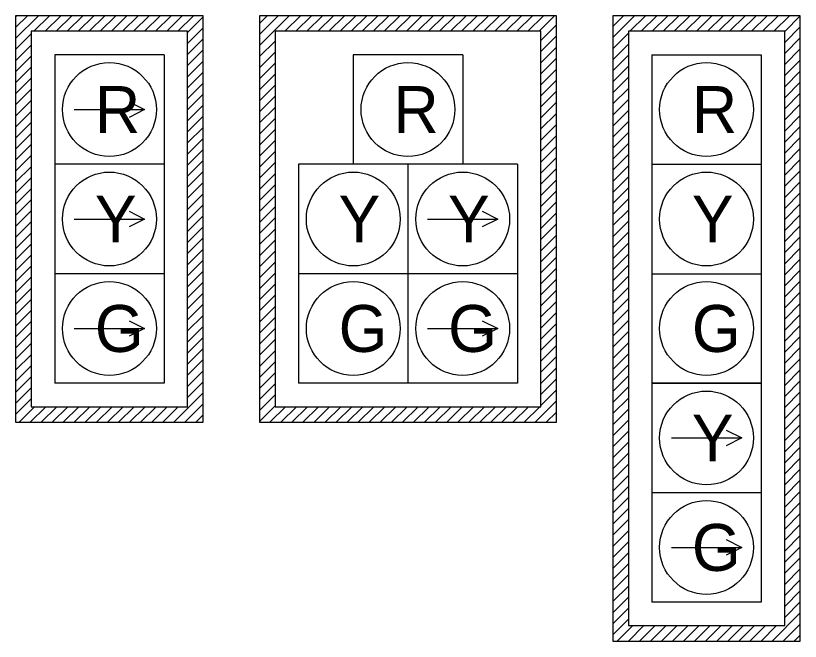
# Model space of a CAD drawing. Extents: x 1736833 to 1738623, y 544707 to 545544.
# Drawn here: x 1737177.5 to 1737277.8, y 545241.6 to 545321.6 of the extents above; entities that cross this region are included whole.
import ezdxf

# ---------------------------------------------------------------- set-up
doc = ezdxf.new("R2010")
doc.units = 0
doc.layers.add('T_Drafting', color=7, linetype='Continuous')

msp = doc.modelspace()

# ---------------------------------------------------------------- linework, layer by layer
at = {"layer": 'T_Drafting'}
for p, q in [((1737201.45, 545321.61), (1737177.45, 545321.61)), ((1737177.45, 545321.61), (1737177.45, 545269.61)), ((1737177.45, 545318.68), (1737180.38, 545321.61)), ((1737177.45, 545320.1), (1737178.97, 545321.61)), ((1737177.45, 545321.51), (1737177.55, 545321.61)), ((1737179.79, 545319.61), (1737181.79, 545321.61)), ((1737181.21, 545319.61), (1737183.21, 545321.61)), ((1737182.62, 545319.61), (1737184.62, 545321.61)), ((1737184.04, 545319.61), (1737186.04, 545321.61)), ((1737185.45, 545319.61), (1737187.45, 545321.61)), ((1737186.87, 545319.61), (1737188.87, 545321.61)), ((1737188.28, 545319.61), (1737190.28, 545321.61)), ((1737189.69, 545319.61), (1737191.69, 545321.61)), ((1737191.11, 545319.61), (1737193.11, 545321.61)), ((1737192.52, 545319.61), (1737194.52, 545321.61)), ((1737193.94, 545319.61), (1737195.94, 545321.61)), ((1737195.35, 545319.61), (1737197.35, 545321.61)), ((1737196.77, 545319.61), (1737198.77, 545321.61)), ((1737198.18, 545319.61), (1737200.18, 545321.61)), ((1737201.45, 545269.61), (1737201.45, 545321.61)), ((1737246.64, 545321.61), (1737208.64, 545321.61)), ((1737208.64, 545321.61), (1737208.64, 545269.61)), ((1737208.64, 545317.79), (1737212.46, 545321.61)), ((1737208.64, 545319.2), (1737211.05, 545321.61)), ((1737208.64, 545320.62), (1737209.63, 545321.61)), ((1737211.88, 545319.61), (1737213.88, 545321.61)), ((1737213.29, 545319.61), (1737215.29, 545321.61)), ((1737214.71, 545319.61), (1737216.71, 545321.61)), ((1737216.12, 545319.61), (1737218.12, 545321.61)), ((1737217.53, 545319.61), (1737219.53, 545321.61)), ((1737218.95, 545319.61), (1737220.95, 545321.61)), ((1737220.36, 545319.61), (1737222.36, 545321.61)), ((1737221.78, 545319.61), (1737223.78, 545321.61)), ((1737223.19, 545319.61), (1737225.19, 545321.61)), ((1737224.6, 545319.61), (1737226.6, 545321.61)), ((1737226.02, 545319.61), (1737228.02, 545321.61)), ((1737227.43, 545319.61), (1737229.43, 545321.61)), ((1737228.85, 545319.61), (1737230.85, 545321.61)), ((1737230.26, 545319.61), (1737232.26, 545321.61)), ((1737231.68, 545319.61), (1737233.68, 545321.61)), ((1737233.09, 545319.61), (1737235.09, 545321.61)), ((1737234.5, 545319.61), (1737236.5, 545321.61)), ((1737235.92, 545319.61), (1737237.92, 545321.61)), ((1737237.33, 545319.61), (1737239.33, 545321.61)), ((1737238.75, 545319.61), (1737240.75, 545321.61)), ((1737240.16, 545319.61), (1737242.16, 545321.61)), ((1737241.58, 545319.61), (1737243.58, 545321.61)), ((1737242.99, 545319.61), (1737244.99, 545321.61)), ((1737244.4, 545319.61), (1737246.4, 545321.61)), ((1737246.64, 545269.61), (1737246.64, 545321.61)), ((1737277.83, 545321.61), (1737253.83, 545321.61)), ((1737253.83, 545321.61), (1737253.83, 545241.61)), ((1737253.83, 545318.81), (1737256.63, 545321.61)), ((1737253.83, 545320.22), (1737255.22, 545321.61)), ((1737256.04, 545319.61), (1737258.04, 545321.61)), ((1737257.46, 545319.61), (1737259.46, 545321.61)), ((1737258.87, 545319.61), (1737260.87, 545321.61)), ((1737260.29, 545319.61), (1737262.29, 545321.61)), ((1737261.7, 545319.61), (1737263.7, 545321.61)), ((1737263.11, 545319.61), (1737265.11, 545321.61)), ((1737264.53, 545319.61), (1737266.53, 545321.61)), ((1737265.94, 545319.61), (1737267.94, 545321.61)), ((1737267.36, 545319.61), (1737269.36, 545321.61)), ((1737268.77, 545319.61), (1737270.77, 545321.61)), ((1737270.19, 545319.61), (1737272.19, 545321.61)), ((1737271.6, 545319.61), (1737273.6, 545321.61)), ((1737273.01, 545319.61), (1737275.01, 545321.61)), ((1737274.43, 545319.61), (1737276.43, 545321.61)), ((1737275.83, 545319.59), (1737277.83, 545321.59)), ((1737277.83, 545241.61), (1737277.83, 545321.61)), ((1737199.45, 545319.47), (1737201.45, 545321.47)), ((1737199.45, 545318.06), (1737201.45, 545320.06)), ((1737244.64, 545318.43), (1737246.64, 545320.43)), ((1737275.83, 545318.18), (1737277.83, 545320.18)), ((1737177.45, 545317.27), (1737179.45, 545319.27)), ((1737199.45, 545316.64), (1737201.45, 545318.64)), ((1737244.64, 545317.02), (1737246.64, 545319.02)), ((1737253.83, 545317.39), (1737255.83, 545319.39)), ((1737275.83, 545316.76), (1737277.83, 545318.76)), ((1737177.45, 545315.85), (1737179.45, 545317.85)), ((1737208.64, 545316.37), (1737210.64, 545318.37)), ((1737244.64, 545315.6), (1737246.64, 545317.6)), ((1737253.83, 545315.98), (1737255.83, 545317.98)), ((1737196.45, 545316.61), (1737182.45, 545316.61)), ((1737182.45, 545316.61), (1737182.45, 545302.61)), ((1737196.45, 545316.61), (1737196.45, 545302.61)), ((1737199.45, 545315.23), (1737201.45, 545317.23)), ((1737208.64, 545314.96), (1737210.64, 545316.96)), ((1737234.64, 545316.61), (1737220.64, 545316.61)), ((1737220.64, 545316.61), (1737220.64, 545302.61)), ((1737234.64, 545316.61), (1737234.64, 545302.61)), ((1737253.83, 545314.56), (1737255.83, 545316.56)), ((1737258.83, 545316.61), (1737272.83, 545316.61)), ((1737258.83, 545316.61), (1737258.83, 545302.61)), ((1737272.83, 545316.61), (1737272.83, 545302.61)), ((1737275.83, 545315.35), (1737277.83, 545317.35)), ((1737177.45, 545314.44), (1737179.45, 545316.44)), ((1737199.45, 545313.81), (1737201.45, 545315.81)), ((1737208.64, 545313.54), (1737210.64, 545315.54)), ((1737244.64, 545314.19), (1737246.64, 545316.19)), ((1737275.83, 545313.94), (1737277.83, 545315.94)), ((1737177.45, 545313.03), (1737179.45, 545315.03)), ((1737244.64, 545312.77), (1737246.64, 545314.77)), ((1737253.83, 545313.15), (1737255.83, 545315.15)), ((1737177.45, 545311.61), (1737179.45, 545313.61)), ((1737199.45, 545312.4), (1737201.45, 545314.4)), ((1737208.64, 545312.13), (1737210.64, 545314.13)), ((1737253.83, 545311.74), (1737255.83, 545313.74)), ((1737275.83, 545312.52), (1737277.83, 545314.52)), ((1737199.45, 545310.98), (1737201.45, 545312.98)), ((1737208.64, 545310.72), (1737210.64, 545312.72)), ((1737244.64, 545311.36), (1737246.64, 545313.36)), ((1737275.83, 545311.11), (1737277.83, 545313.11)), ((1737177.45, 545310.2), (1737179.45, 545312.2)), ((1737199.45, 545309.57), (1737201.45, 545311.57)), ((1737244.64, 545309.95), (1737246.64, 545311.95)), ((1737253.83, 545310.32), (1737255.83, 545312.32)), ((1737275.83, 545309.69), (1737277.83, 545311.69)), ((1737177.45, 545308.78), (1737179.45, 545310.78)), ((1737208.64, 545309.3), (1737210.64, 545311.3)), ((1737244.64, 545308.53), (1737246.64, 545310.53)), ((1737253.83, 545308.91), (1737255.83, 545310.91)), ((1737184.95, 545309.61), (1737193.95, 545309.61)), ((1737199.45, 545308.16), (1737201.45, 545310.16)), ((1737208.64, 545307.89), (1737210.64, 545309.89)), ((1737275.83, 545308.28), (1737277.83, 545310.28)), ((1737177.45, 545307.37), (1737179.45, 545309.37)), ((1737199.45, 545306.74), (1737201.45, 545308.74)), ((1737244.64, 545307.12), (1737246.64, 545309.12)), ((1737253.83, 545307.49), (1737255.83, 545309.49)), ((1737275.83, 545306.86), (1737277.83, 545308.86)), ((1737177.45, 545305.96), (1737179.45, 545307.96)), ((1737208.64, 545306.47), (1737210.64, 545308.47)), ((1737244.64, 545305.7), (1737246.64, 545307.7)), ((1737253.83, 545306.08), (1737255.83, 545308.08)), ((1737177.45, 545304.54), (1737179.45, 545306.54)), ((1737199.45, 545305.33), (1737201.45, 545307.33)), ((1737208.64, 545305.06), (1737210.64, 545307.06)), ((1737253.83, 545304.66), (1737255.83, 545306.66)), ((1737275.83, 545305.45), (1737277.83, 545307.45)), ((1737199.45, 545303.91), (1737201.45, 545305.91)), ((1737208.64, 545303.64), (1737210.64, 545305.64)), ((1737244.64, 545304.29), (1737246.64, 545306.29)), ((1737275.83, 545304.04), (1737277.83, 545306.04)), ((1737177.45, 545303.13), (1737179.45, 545305.13)), ((1737199.45, 545302.5), (1737201.45, 545304.5)), ((1737244.64, 545302.88), (1737246.64, 545304.88)), ((1737253.83, 545303.25), (1737255.83, 545305.25)), ((1737275.83, 545302.62), (1737277.83, 545304.62)), ((1737177.45, 545301.71), (1737179.45, 545303.71)), ((1737208.64, 545302.23), (1737210.64, 545304.23)), ((1737253.83, 545301.84), (1737255.83, 545303.84)), ((1737196.45, 545302.61), (1737182.45, 545302.61)), ((1737182.45, 545302.61), (1737182.45, 545288.61)), ((1737196.45, 545302.61), (1737196.45, 545288.61)), ((1737199.45, 545301.08), (1737201.45, 545303.08)), ((1737208.64, 545300.82), (1737210.64, 545302.82)), ((1737227.64, 545302.61), (1737213.64, 545302.61)), ((1737213.64, 545302.61), (1737213.64, 545288.61)), ((1737227.64, 545302.61), (1737227.64, 545288.61)), ((1737241.64, 545302.61), (1737227.64, 545302.61)), ((1737227.64, 545302.61), (1737227.64, 545288.61)), ((1737241.64, 545302.61), (1737241.64, 545288.61)), ((1737244.64, 545301.46), (1737246.64, 545303.46)), ((1737258.83, 545302.61), (1737272.83, 545302.61)), ((1737258.83, 545302.61), (1737258.83, 545288.61)), ((1737272.83, 545302.61), (1737272.83, 545288.61)), ((1737275.83, 545301.21), (1737277.83, 545303.21)), ((1737177.45, 545300.3), (1737179.45, 545302.3)), ((1737199.45, 545299.67), (1737201.45, 545301.67)), ((1737244.64, 545300.05), (1737246.64, 545302.05)), ((1737253.83, 545300.42), (1737255.83, 545302.42)), ((1737275.83, 545299.79), (1737277.83, 545301.79)), ((1737177.45, 545298.88), (1737179.45, 545300.88)), ((1737208.64, 545299.4), (1737210.64, 545301.4)), ((1737244.64, 545298.63), (1737246.64, 545300.63)), ((1737253.83, 545299.01), (1737255.83, 545301.01)), ((1737199.45, 545298.26), (1737201.45, 545300.26)), ((1737208.64, 545297.99), (1737210.64, 545299.99)), ((1737253.83, 545297.59), (1737255.83, 545299.59)), ((1737275.83, 545298.38), (1737277.83, 545300.38)), ((1737177.45, 545297.47), (1737179.45, 545299.47)), ((1737199.45, 545296.84), (1737201.45, 545298.84)), ((1737208.64, 545296.57), (1737210.64, 545298.57)), ((1737244.64, 545297.22), (1737246.64, 545299.22)), ((1737275.83, 545296.97), (1737277.83, 545298.97)), ((1737177.45, 545296.06), (1737179.45, 545298.06)), ((1737244.64, 545295.8), (1737246.64, 545297.8)), ((1737253.83, 545296.18), (1737255.83, 545298.18)), ((1737275.83, 545295.55), (1737277.83, 545297.55)), ((1737177.45, 545294.64), (1737179.45, 545296.64)), ((1737199.45, 545295.43), (1737201.45, 545297.43)), ((1737208.64, 545295.16), (1737210.64, 545297.16)), ((1737253.83, 545294.76), (1737255.83, 545296.76)), ((1737184.95, 545295.61), (1737193.95, 545295.61)), ((1737199.45, 545294.01), (1737201.45, 545296.01)), ((1737208.64, 545293.75), (1737210.64, 545295.75)), ((1737230.14, 545295.61), (1737239.14, 545295.61)), ((1737244.64, 545294.39), (1737246.64, 545296.39)), ((1737275.83, 545294.14), (1737277.83, 545296.14)), ((1737177.45, 545293.23), (1737179.45, 545295.23)), ((1737199.45, 545292.6), (1737201.45, 545294.6)), ((1737244.64, 545292.98), (1737246.64, 545294.98)), ((1737253.83, 545293.35), (1737255.83, 545295.35)), ((1737275.83, 545292.72), (1737277.83, 545294.72)), ((1737177.45, 545291.81), (1737179.45, 545293.81)), ((1737208.64, 545292.33), (1737210.64, 545294.33)), ((1737244.64, 545291.56), (1737246.64, 545293.56)), ((1737253.83, 545291.94), (1737255.83, 545293.94)), ((1737199.45, 545291.19), (1737201.45, 545293.19)), ((1737208.64, 545290.92), (1737210.64, 545292.92)), ((1737253.83, 545290.52), (1737255.83, 545292.52)), ((1737275.83, 545291.31), (1737277.83, 545293.31)), ((1737177.45, 545290.4), (1737179.45, 545292.4)), ((1737199.45, 545289.77), (1737201.45, 545291.77)), ((1737208.64, 545289.5), (1737210.64, 545291.5)), ((1737244.64, 545290.15), (1737246.64, 545292.15)), ((1737275.83, 545289.89), (1737277.83, 545291.89)), ((1737177.45, 545288.98), (1737179.45, 545290.98)), ((1737244.64, 545288.73), (1737246.64, 545290.73)), ((1737253.83, 545289.11), (1737255.83, 545291.11)), ((1737275.83, 545288.48), (1737277.83, 545290.48)), ((1737177.45, 545287.57), (1737179.45, 545289.57)), ((1737199.45, 545288.36), (1737201.45, 545290.36)), ((1737208.64, 545288.09), (1737210.64, 545290.09)), ((1737253.83, 545287.69), (1737255.83, 545289.69)), ((1737196.45, 545288.61), (1737182.45, 545288.61)), ((1737182.45, 545288.61), (1737182.45, 545274.61)), ((1737196.45, 545288.61), (1737196.45, 545274.61)), ((1737199.45, 545286.94), (1737201.45, 545288.94)), ((1737208.64, 545286.67), (1737210.64, 545288.67)), ((1737227.64, 545288.61), (1737213.64, 545288.61)), ((1737213.64, 545288.61), (1737213.64, 545274.61)), ((1737241.64, 545288.61), (1737227.64, 545288.61)), ((1737227.64, 545288.61), (1737227.64, 545274.61)), ((1737227.64, 545288.61), (1737227.64, 545274.61)), ((1737241.64, 545288.61), (1737241.64, 545274.61)), ((1737244.64, 545287.32), (1737246.64, 545289.32)), ((1737258.83, 545288.61), (1737272.83, 545288.61)), ((1737258.83, 545288.61), (1737258.83, 545274.61)), ((1737272.83, 545288.61), (1737272.83, 545274.61)), ((1737275.83, 545287.07), (1737277.83, 545289.07)), ((1737177.45, 545286.16), (1737179.45, 545288.16)), ((1737199.45, 545285.53), (1737201.45, 545287.53)), ((1737244.64, 545285.9), (1737246.64, 545287.9)), ((1737253.83, 545286.28), (1737255.83, 545288.28)), ((1737275.83, 545285.65), (1737277.83, 545287.65)), ((1737177.45, 545284.74), (1737179.45, 545286.74)), ((1737208.64, 545285.26), (1737210.64, 545287.26)), ((1737244.64, 545284.49), (1737246.64, 545286.49)), ((1737253.83, 545284.86), (1737255.83, 545286.86)), ((1737199.45, 545284.11), (1737201.45, 545286.11)), ((1737208.64, 545283.85), (1737210.64, 545285.85)), ((1737253.83, 545283.45), (1737255.83, 545285.45)), ((1737275.83, 545284.24), (1737277.83, 545286.24)), ((1737177.45, 545283.33), (1737179.45, 545285.33)), ((1737199.45, 545282.7), (1737201.45, 545284.7)), ((1737208.64, 545282.43), (1737210.64, 545284.43)), ((1737244.64, 545283.08), (1737246.64, 545285.08)), ((1737275.83, 545282.82), (1737277.83, 545284.82)), ((1737177.45, 545281.91), (1737179.45, 545283.91)), ((1737244.64, 545281.66), (1737246.64, 545283.66)), ((1737253.83, 545282.04), (1737255.83, 545284.04)), ((1737177.45, 545280.5), (1737179.45, 545282.5)), ((1737199.45, 545281.29), (1737201.45, 545283.29)), ((1737208.64, 545281.02), (1737210.64, 545283.02)), ((1737253.83, 545280.62), (1737255.83, 545282.62)), ((1737275.83, 545281.41), (1737277.83, 545283.41)), ((1737184.95, 545281.61), (1737193.95, 545281.61)), ((1737199.45, 545279.87), (1737201.45, 545281.87)), ((1737208.64, 545279.6), (1737210.64, 545281.6)), ((1737230.14, 545281.61), (1737239.14, 545281.61)), ((1737244.64, 545280.25), (1737246.64, 545282.25)), ((1737275.83, 545279.99), (1737277.83, 545281.99)), ((1737177.45, 545279.08), (1737179.45, 545281.08)), ((1737199.45, 545278.46), (1737201.45, 545280.46)), ((1737244.64, 545278.83), (1737246.64, 545280.83)), ((1737253.83, 545279.21), (1737255.83, 545281.21)), ((1737275.83, 545278.58), (1737277.83, 545280.58)), ((1737177.45, 545277.67), (1737179.45, 545279.67)), ((1737208.64, 545278.19), (1737210.64, 545280.19)), ((1737244.64, 545277.42), (1737246.64, 545279.42)), ((1737253.83, 545277.79), (1737255.83, 545279.79)), ((1737199.45, 545277.04), (1737201.45, 545279.04)), ((1737208.64, 545276.77), (1737210.64, 545278.77)), ((1737275.83, 545277.17), (1737277.83, 545279.17)), ((1737177.45, 545276.26), (1737179.45, 545278.26)), ((1737199.45, 545275.63), (1737201.45, 545277.63)), ((1737244.64, 545276.01), (1737246.64, 545278.01)), ((1737253.83, 545276.38), (1737255.83, 545278.38)), ((1737275.83, 545275.75), (1737277.83, 545277.75)), ((1737177.45, 545274.84), (1737179.45, 545276.84)), ((1737208.64, 545275.36), (1737210.64, 545277.36)), ((1737244.64, 545274.59), (1737246.64, 545276.59)), ((1737253.83, 545274.97), (1737255.83, 545276.97)), ((1737177.45, 545273.43), (1737179.45, 545275.43)), ((1737199.45, 545274.21), (1737201.45, 545276.21)), ((1737208.64, 545273.95), (1737210.64, 545275.95)), ((1737253.83, 545273.55), (1737255.83, 545275.55)), ((1737275.83, 545274.34), (1737277.83, 545276.34)), ((1737196.45, 545274.61), (1737182.45, 545274.61)), ((1737199.45, 545272.8), (1737201.45, 545274.8)), ((1737208.64, 545272.53), (1737210.64, 545274.53)), ((1737227.64, 545274.61), (1737213.64, 545274.61)), ((1737241.64, 545274.61), (1737227.64, 545274.61)), ((1737244.64, 545273.18), (1737246.64, 545275.18)), ((1737258.83, 545274.61), (1737272.83, 545274.61)), ((1737272.83, 545274.61), (1737258.83, 545274.61)), ((1737258.83, 545274.61), (1737258.83, 545260.61)), ((1737272.83, 545274.61), (1737272.83, 545260.61)), ((1737275.83, 545272.92), (1737277.83, 545274.92)), ((1737177.45, 545272.01), (1737179.45, 545274.01)), ((1737197.68, 545269.61), (1737201.45, 545273.39)), ((1737244.64, 545271.76), (1737246.64, 545273.76)), ((1737253.83, 545272.14), (1737255.83, 545274.14)), ((1737275.83, 545271.51), (1737277.83, 545273.51)), ((1737177.45, 545270.6), (1737179.45, 545272.6)), ((1737208.64, 545271.12), (1737210.64, 545273.12)), ((1737253.83, 545270.72), (1737255.83, 545272.72)), ((1737177.88, 545269.61), (1737179.88, 545271.61)), ((1737179.29, 545269.61), (1737181.29, 545271.61)), ((1737180.71, 545269.61), (1737182.71, 545271.61)), ((1737182.12, 545269.61), (1737184.12, 545271.61)), ((1737183.53, 545269.61), (1737185.53, 545271.61)), ((1737184.95, 545269.61), (1737186.95, 545271.61)), ((1737186.36, 545269.61), (1737188.36, 545271.61)), ((1737187.78, 545269.61), (1737189.78, 545271.61)), ((1737189.19, 545269.61), (1737191.19, 545271.61)), ((1737190.61, 545269.61), (1737192.61, 545271.61)), ((1737192.02, 545269.61), (1737194.02, 545271.61)), ((1737193.43, 545269.61), (1737195.43, 545271.61)), ((1737194.85, 545269.61), (1737196.85, 545271.61)), ((1737196.26, 545269.61), (1737198.26, 545271.61)), ((1737199.09, 545269.61), (1737201.45, 545271.97)), ((1737208.64, 545269.7), (1737210.64, 545271.7)), ((1737209.96, 545269.61), (1737211.96, 545271.61)), ((1737211.37, 545269.61), (1737213.37, 545271.61)), ((1737212.79, 545269.61), (1737214.79, 545271.61)), ((1737214.2, 545269.61), (1737216.2, 545271.61)), ((1737215.62, 545269.61), (1737217.62, 545271.61)), ((1737217.03, 545269.61), (1737219.03, 545271.61)), ((1737218.45, 545269.61), (1737220.45, 545271.61)), ((1737219.86, 545269.61), (1737221.86, 545271.61)), ((1737221.27, 545269.61), (1737223.27, 545271.61)), ((1737222.69, 545269.61), (1737224.69, 545271.61)), ((1737224.1, 545269.61), (1737226.1, 545271.61)), ((1737225.52, 545269.61), (1737227.52, 545271.61)), ((1737226.93, 545269.61), (1737228.93, 545271.61)), ((1737228.34, 545269.61), (1737230.34, 545271.61)), ((1737229.76, 545269.61), (1737231.76, 545271.61)), ((1737231.17, 545269.61), (1737233.17, 545271.61)), ((1737232.59, 545269.61), (1737234.59, 545271.61)), ((1737234, 545269.61), (1737236, 545271.61)), ((1737235.42, 545269.61), (1737237.42, 545271.61)), ((1737236.83, 545269.61), (1737238.83, 545271.61)), ((1737238.24, 545269.61), (1737240.24, 545271.61)), ((1737239.66, 545269.61), (1737241.66, 545271.61)), ((1737241.07, 545269.61), (1737243.07, 545271.61)), ((1737242.49, 545269.61), (1737244.49, 545271.61)), ((1737243.9, 545269.61), (1737246.64, 545272.35)), ((1737275.83, 545270.1), (1737277.83, 545272.1)), ((1737200.51, 545269.61), (1737201.45, 545270.56)), ((1737245.32, 545269.61), (1737246.64, 545270.93)), ((1737253.83, 545269.31), (1737255.83, 545271.31)), ((1737275.83, 545268.68), (1737277.83, 545270.68)), ((1737177.45, 545269.61), (1737201.45, 545269.61)), ((1737208.64, 545269.61), (1737246.64, 545269.61)), ((1737253.83, 545267.89), (1737255.83, 545269.89)), ((1737253.83, 545266.48), (1737255.83, 545268.48)), ((1737275.83, 545267.27), (1737277.83, 545269.27)), ((1737261.33, 545267.61), (1737270.33, 545267.61)), ((1737275.83, 545265.85), (1737277.83, 545267.85)), ((1737253.83, 545265.07), (1737255.83, 545267.07)), ((1737275.83, 545264.44), (1737277.83, 545266.44)), ((1737253.83, 545263.65), (1737255.83, 545265.65)), ((1737275.83, 545263.02), (1737277.83, 545265.02)), ((1737253.83, 545262.24), (1737255.83, 545264.24)), ((1737275.83, 545261.61), (1737277.83, 545263.61)), ((1737253.83, 545260.82), (1737255.83, 545262.82)), ((1737253.83, 545259.41), (1737255.83, 545261.41)), ((1737275.83, 545260.2), (1737277.83, 545262.2)), ((1737272.83, 545260.61), (1737258.83, 545260.61)), ((1737258.83, 545260.61), (1737258.83, 545246.61)), ((1737272.83, 545260.61), (1737272.83, 545246.61)), ((1737275.83, 545258.78), (1737277.83, 545260.78)), ((1737253.83, 545257.99), (1737255.83, 545259.99)), ((1737275.83, 545257.37), (1737277.83, 545259.37)), ((1737253.83, 545256.58), (1737255.83, 545258.58)), ((1737275.83, 545255.95), (1737277.83, 545257.95)), ((1737253.83, 545255.17), (1737255.83, 545257.17)), ((1737275.83, 545254.54), (1737277.83, 545256.54)), ((1737253.83, 545253.75), (1737255.83, 545255.75)), ((1737253.83, 545252.34), (1737255.83, 545254.34)), ((1737275.83, 545253.12), (1737277.83, 545255.12)), ((1737261.33, 545253.61), (1737270.33, 545253.61)), ((1737275.83, 545251.71), (1737277.83, 545253.71)), ((1737253.83, 545250.92), (1737255.83, 545252.92)), ((1737253.83, 545249.51), (1737255.83, 545251.51)), ((1737275.83, 545250.3), (1737277.83, 545252.3)), ((1737275.83, 545248.88), (1737277.83, 545250.88)), ((1737253.83, 545248.1), (1737255.83, 545250.1)), ((1737275.83, 545247.47), (1737277.83, 545249.47)), ((1737253.83, 545246.68), (1737255.83, 545248.68)), ((1737275.83, 545246.05), (1737277.83, 545248.05)), ((1737253.83, 545245.27), (1737255.83, 545247.27)), ((1737272.83, 545246.61), (1737258.83, 545246.61)), ((1737275.83, 545244.64), (1737277.83, 545246.64)), ((1737253.83, 545243.85), (1737255.83, 545245.85)), ((1737253.83, 545242.44), (1737255.83, 545244.44)), ((1737274.21, 545241.61), (1737277.83, 545245.23)), ((1737254.41, 545241.61), (1737256.41, 545243.61)), ((1737255.83, 545241.61), (1737257.83, 545243.61)), ((1737257.24, 545241.61), (1737259.24, 545243.61)), ((1737258.65, 545241.61), (1737260.65, 545243.61)), ((1737260.07, 545241.61), (1737262.07, 545243.61)), ((1737261.48, 545241.61), (1737263.48, 545243.61)), ((1737262.9, 545241.61), (1737264.9, 545243.61)), ((1737264.31, 545241.61), (1737266.31, 545243.61)), ((1737265.72, 545241.61), (1737267.72, 545243.61)), ((1737267.14, 545241.61), (1737269.14, 545243.61)), ((1737268.55, 545241.61), (1737270.55, 545243.61)), ((1737269.97, 545241.61), (1737271.97, 545243.61)), ((1737271.38, 545241.61), (1737273.38, 545243.61)), ((1737272.8, 545241.61), (1737274.8, 545243.61)), ((1737275.62, 545241.61), (1737277.83, 545243.81)), ((1737277.04, 545241.61), (1737277.83, 545242.4)), ((1737253.83, 545241.61), (1737277.83, 545241.61))]:
    msp.add_line(p, q, dxfattribs=at)
for points in [[(1737199.45, 545319.61), (1737179.45, 545319.61), (1737179.45, 545271.61), (1737199.45, 545271.61)], [(1737244.64, 545319.61), (1737210.64, 545319.61), (1737210.64, 545271.61), (1737244.64, 545271.61)], [(1737275.83, 545319.61), (1737255.83, 545319.61), (1737255.83, 545243.61), (1737275.83, 545243.61)]]:
    msp.add_lwpolyline(points, close=True, dxfattribs=at)
for points in [[(1737191.95, 545310.61), (1737193.95, 545309.61), (1737191.95, 545308.61)], [(1737191.95, 545296.61), (1737193.95, 545295.61), (1737191.95, 545294.61)], [(1737237.14, 545296.61), (1737239.14, 545295.61), (1737237.14, 545294.61)], [(1737191.95, 545282.61), (1737193.95, 545281.61), (1737191.95, 545280.61)], [(1737237.14, 545282.61), (1737239.14, 545281.61), (1737237.14, 545280.61)], [(1737268.33, 545268.61), (1737270.33, 545267.61), (1737268.33, 545266.61)], [(1737268.33, 545254.61), (1737270.33, 545253.61), (1737268.33, 545252.61)]]:
    msp.add_lwpolyline(points, dxfattribs=at)
for centre in [(1737189.45, 545309.61), (1737227.64, 545309.61), (1737265.83, 545309.61), (1737189.45, 545295.61), (1737220.64, 545295.61), (1737234.64, 545295.61), (1737265.83, 545295.61), (1737189.45, 545281.61), (1737220.64, 545281.61), (1737234.64, 545281.61), (1737265.83, 545281.61), (1737265.83, 545267.61), (1737265.83, 545253.61)]:
    msp.add_circle(centre, 6, dxfattribs=at)

# ---------------------------------------------------------------- texts
for s, p in [('R', (1737187.59, 545306.61)), ('R', (1737225.78, 545306.61)), ('R', (1737263.96, 545306.61)), ('Y', (1737187.57, 545292.61)), ('Y', (1737218.75, 545292.61)), ('Y', (1737232.75, 545292.61)), ('Y', (1737263.94, 545292.61)), ('G', (1737187.59, 545278.61)), ('G', (1737218.77, 545278.61)), ('G', (1737232.77, 545278.61)), ('G', (1737263.96, 545278.61)), ('Y', (1737263.94, 545264.61)), ('G', (1737263.96, 545250.61))]:
    msp.add_text(s, height=6, dxfattribs=at).set_placement(p)

doc.saveas('drawing.dxf')
